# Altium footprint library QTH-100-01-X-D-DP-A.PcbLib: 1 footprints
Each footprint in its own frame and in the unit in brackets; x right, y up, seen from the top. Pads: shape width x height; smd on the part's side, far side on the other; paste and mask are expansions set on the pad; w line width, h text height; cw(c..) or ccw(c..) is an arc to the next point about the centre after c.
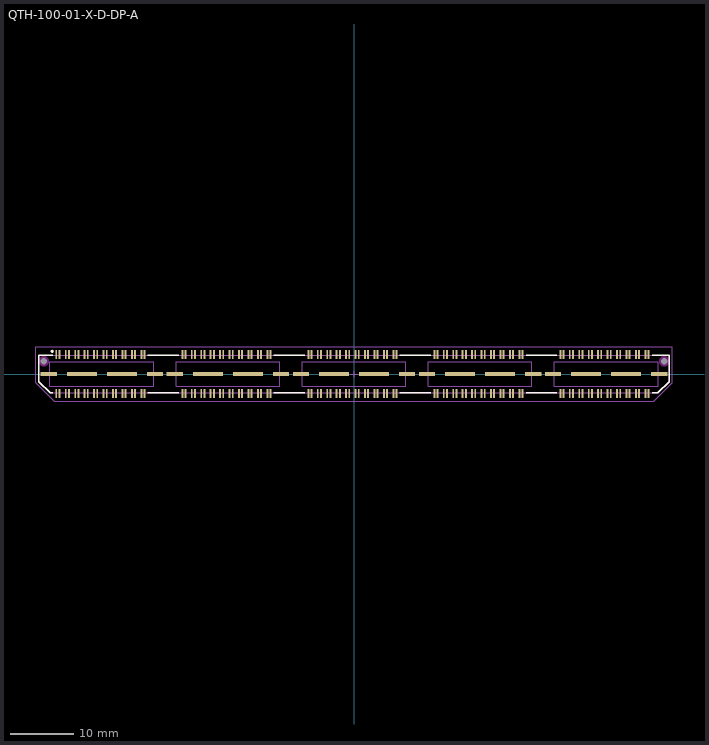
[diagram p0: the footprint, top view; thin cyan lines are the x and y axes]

## QTH-100-01-X-D-DP-A [mm] "0.50mm pitch, 200 pin, high speed terminal strip; differential"
height 4.27
pads (222):
  rect 0.3x1.45 smd mask+0: 1(-47.25,3.09) 2(-47.25,-3.09) 3(-46.75,3.09) 4(-46.75,-3.09) 5(-45.75,3.09) 6(-45.75,-3.09) 7(-45.25,3.09) 8(-45.25,-3.09) 9(-44.25,3.09) 10(-44.25,-3.09) 11(-43.75,3.09) 12(-43.75,-3.09) 13(-42.75,3.09) 14(-42.75,-3.09) 15(-42.25,3.09) 16(-42.25,-3.09) 17(-41.25,3.09) 18(-41.25,-3.09) 19(-40.75,3.09) 20(-40.75,-3.09) 21(-39.75,3.09) 22(-39.75,-3.09) 23(-39.25,3.09) 24(-39.25,-3.09) 25(-38.25,3.09) 26(-38.25,-3.09) 27(-37.75,3.09) 28(-37.75,-3.09) 29(-36.75,3.09) 30(-36.75,-3.09) 31(-36.25,3.09) 32(-36.25,-3.09) 33(-35.25,3.09) 34(-35.25,-3.09) 35(-34.75,3.09) 36(-34.75,-3.09) 37(-33.75,3.09) 38(-33.75,-3.09) 39(-33.25,3.09) 40(-33.25,-3.09) 41(-27.25,3.09) 42(-27.25,-3.09) 43(-26.75,3.09) 44(-26.75,-3.09) 45(-25.75,3.09) 46(-25.75,-3.09) 47(-25.25,3.09) 48(-25.25,-3.09) 49(-24.25,3.09) 50(-24.25,-3.09) 51(-23.75,3.09) 52(-23.75,-3.09) 53(-22.75,3.09) 54(-22.75,-3.09) 55(-22.25,3.09) 56(-22.25,-3.09) 57(-21.25,3.09) 58(-21.25,-3.09) 59(-20.75,3.09) 60(-20.75,-3.09) 61(-19.75,3.09) 62(-19.75,-3.09) 63(-19.25,3.09) 64(-19.25,-3.09) 65(-18.25,3.09) 66(-18.25,-3.09) 67(-17.75,3.09) 68(-17.75,-3.09) 69(-16.75,3.09) 70(-16.75,-3.09) 71(-16.25,3.09) 72(-16.25,-3.09) 73(-15.25,3.09) 74(-15.25,-3.09) 75(-14.75,3.09) 76(-14.75,-3.09) 77(-13.75,3.09) 78(-13.75,-3.09) 79(-13.25,3.09) 80(-13.25,-3.09) 81(-7.25,3.09) 82(-7.25,-3.09) 83(-6.75,3.09) 84(-6.75,-3.09) 85(-5.75,3.09) 86(-5.75,-3.09) 87(-5.25,3.09) 88(-5.25,-3.09) 89(-4.25,3.09) 90(-4.25,-3.09) 91(-3.75,3.09) 92(-3.75,-3.09) 93(-2.75,3.09) 94(-2.75,-3.09) 95(-2.25,3.09) 96(-2.25,-3.09) 97(-1.25,3.09) 98(-1.25,-3.09) 99(-0.75,3.09) 100(-0.75,-3.09) 101(0.25,3.09) 102(0.25,-3.09) 103(0.75,3.09) 104(0.75,-3.09) 105(1.75,3.09) 106(1.75,-3.09) 107(2.25,3.09) 108(2.25,-3.09) 109(3.25,3.09) 110(3.25,-3.09) 111(3.75,3.09) 112(3.75,-3.09) 113(4.75,3.09) 114(4.75,-3.09) 115(5.25,3.09) 116(5.25,-3.09) 117(6.25,3.09) 118(6.25,-3.09) 119(6.75,3.09) 120(6.75,-3.09) 121(12.75,3.09) 122(12.75,-3.09) 123(13.25,3.09) 124(13.25,-3.09) 125(14.25,3.09) 126(14.25,-3.09) 127(14.75,3.09) 128(14.75,-3.09) 129(15.75,3.09) 130(15.75,-3.09) 131(16.25,3.09) 132(16.25,-3.09) 133(17.25,3.09) 134(17.25,-3.09) 135(17.75,3.09) 136(17.75,-3.09) 137(18.75,3.09) 138(18.75,-3.09) 139(19.25,3.09) 140(19.25,-3.09) 141(20.25,3.09) 142(20.25,-3.09) 143(20.75,3.09) 144(20.75,-3.09) 145(21.75,3.09) 146(21.75,-3.09) 147(22.25,3.09) 148(22.25,-3.09) 149(23.25,3.09) 150(23.25,-3.09) 151(23.75,3.09) 152(23.75,-3.09) 153(24.75,3.09) 154(24.75,-3.09) 155(25.25,3.09) 156(25.25,-3.09) 157(26.25,3.09) 158(26.25,-3.09) 159(26.75,3.09) 160(26.75,-3.09) 161(32.75,3.09) 162(32.75,-3.09) 163(33.25,3.09) 164(33.25,-3.09) 165(34.25,3.09) 166(34.25,-3.09) 167(34.75,3.09) 168(34.75,-3.09) 169(35.75,3.09) 170(35.75,-3.09) 171(36.25,3.09) 172(36.25,-3.09) 173(37.25,3.09) 174(37.25,-3.09) 175(37.75,3.09) 176(37.75,-3.09) 177(38.75,3.09) 178(38.75,-3.09) 179(39.25,3.09) 180(39.25,-3.09) 181(40.25,3.09) 182(40.25,-3.09) 183(40.75,3.09) 184(40.75,-3.09) 185(41.75,3.09) 186(41.75,-3.09) 187(42.25,3.09) 188(42.25,-3.09) 189(43.25,3.09) 190(43.25,-3.09) 191(43.75,3.09) 192(43.75,-3.09) 193(44.75,3.09) 194(44.75,-3.09) 195(45.25,3.09) 196(45.25,-3.09) 197(46.25,3.09) 198(46.25,-3.09) 199(46.75,3.09) 200(46.75,-3.09)
  rect 2.55x0.65 smd mask+0: 201(-48.445,0) 204(-31.555,0) 205(-28.445,0) 208(-11.555,0) 209(-8.445,0) 212(8.445,0) 213(11.555,0) 216(28.445,0) 217(31.555,0) 220(48.445,0)
  rect 4.7x0.65 smd mask+0: 202(-43.175,0) 203(-36.825,0) 206(-23.175,0) 207(-16.825,0) 210(-3.175,0) 211(3.175,0) 214(16.825,0) 215(23.175,0) 218(36.825,0) 219(43.175,0)
  round 0.5 hole 1 unplated mask+0: 221(-49.24,2.03) 222(49.24,2.03)
Top Overlay:
  circle w0.25: c-47.9,3.6 r0.125
  lines w0.2: -47.8,-3 -48.2,-3 -50,-1.2 -50,3 -47.8,3 ; -32.7,-3 -27.8,-3 ; -32.7,3 -27.8,3 ; -12.7,-3 -7.8,-3 ; -12.7,3 -7.8,3 ; 7.3,-3 12.2,-3 ; 7.3,3 12.2,3 ; 27.3,-3 32.2,-3 ; 27.3,3 32.2,3 ; 47.3,-3 48.2,-3 50,-1.2 50,3 47.3,3
Keep-Out Layer:
  pour cut-out: -48.433,2.03 -48.461,2.239 -48.541,2.433 -48.669,2.601 -48.837,2.729 -49.031,2.809 -49.24,2.837 -49.449,2.809 -49.643,2.729 -49.811,2.601 -49.939,2.433 -50.019,2.239 -50.047,2.03 -50.019,1.821 -49.939,1.627 -49.811,1.459 -49.643,1.331 -49.449,1.251 -49.24,1.223 -49.031,1.251 -48.837,1.331 -48.669,1.459 -48.541,1.627 -48.461,1.821
  pour cut-out: 50.047,2.03 50.019,2.239 49.939,2.433 49.811,2.601 49.643,2.729 49.449,2.809 49.24,2.837 49.031,2.809 48.837,2.729 48.669,2.601 48.541,2.433 48.461,2.239 48.433,2.03 48.461,1.821 48.541,1.627 48.669,1.459 48.837,1.331 49.031,1.251 49.24,1.223 49.449,1.251 49.643,1.331 49.811,1.459 49.939,1.627 50.019,1.821
Mechanical 12:
  lines w0.001: -50,-1.2 -48.2,-3 48.2,-3 50,-1.2 50,3 -50,3 -50,-1.2
Mechanical 13:
  lines w0.1: -50,-1.2 -48.2,-3 48.2,-3 50,-1.2 50,3 -50,3 -50,-1.2 ; -48.25,-1.95 -31.75,-1.95 -31.75,1.95 -48.25,1.95 -48.25,-1.95 ; -28.25,-1.95 -11.75,-1.95 -11.75,1.95 -28.25,1.95 -28.25,-1.95 ; -8.25,-1.95 8.25,-1.95 8.25,1.95 -8.25,1.95 -8.25,-1.95 ; 11.75,-1.95 28.25,-1.95 28.25,1.95 11.75,1.95 11.75,-1.95 ; 31.75,-1.95 48.25,-1.95 48.25,1.95 31.75,1.95 31.75,-1.95
  text ".Designator" at 0.127,0 h1.52
Mechanical 15:
  lines w0.05: -0.5,0 0.5,0 ; 0,-0.5 0,0.5 ; -50.5,-1.4 -47.6,-4.3 47.6,-4.3 50.5,-1.4 50.5,4.3 -50.5,4.3 -50.5,-1.4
